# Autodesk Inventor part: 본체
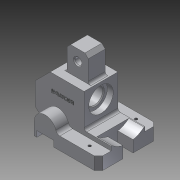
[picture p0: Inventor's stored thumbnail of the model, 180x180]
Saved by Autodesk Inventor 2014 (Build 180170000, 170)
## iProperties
Created: 2016-11
Part Number: 본체
Material: Aluminum 6061
Document SubType Name: Modeling
Designer: user
Density: 2.71 g/cm^3
Appearance: Aluminum - Flat
Mass: 462.896 g
Surface Area: 317.14 cm^2
Volume: 170.81 cm^3
Author: user
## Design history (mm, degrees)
sketch "Sketch2"
  geometry: L1 (0, 0)-(63, 0); L2 (-13, 15)-(13, 15); L3 (-13, 15)-(-13, 0); L4 (0, 0)-(-13, 0); L5 (-10, 0)-(-10, 7); L6 (-10, 7)-(10, 7); L7 (10, 7)-(10, 0); L8 (13, 15)-(38.139, 15); L9 (-13, 0)-(-10, 0); L10 (63, 0)-(63, 15); L11 (38.139, 15)-(63, 15); A1 r 13 centre (0, 15) between (13, 15) and (-13, 15); 2 further points
  constraints: 22 end point, 7 perpendicular, 2 midpoint, 2 point on circle, 2 point on line, 1 centre point, 1 coincident, 1 collinear, 1 horizontal, 1 parallel, 1 tangent, 1 vertical alignment
  dimensions: "d0" = 26 diameter of A1; "d1" = 15 distance of L1.start A1.centre; "d2" = 7 distance of L5.start L5.end; "d3" = 20 distance of L5.end L6.end; "d4" = 63 distance of L1.end L1.start; "d5" = 15 distance of L1.end L10.end; "d6" = 3 distance between parallel lines of L5 L3
extrude "Extrusion1" new body sketch "Sketch2" stored distance "d7" = 70; taper "d8" = 0 deg
fillet "Fillet1" dims "d9" = 5
sketch "Sketch3"
  geometry: L1 (17.292, 15)-(63, 15) reference; L2 (63, 15)-(63, 0) reference; L3 (-13, 0)-(-13, 15) reference; L4 (63, 15)-(63, 20); L5 (-27, 12)-(-27, 42); L6 (31, 20)-(31, 60); L7 (26, 42)-(26, 60); L8 (-9, 60)-(31, 60); L9 (63, 0)-(10, 0) reference; L10 (-27, 12)-(-13, 12); L11 (-27, 42)-(31, 42); L12 (-27, 42)-(-9, 60); L13 (63, 15)-(17.292, 15) reference; L14 (31, 20)-(63, 20); A1 r 13 centre (0, 15) between (12.488, 18.611) and (-13, 15) reference; A2 r 5 centre (17.292, 20) between (12.488, 18.611) and (17.292, 15) reference; 3 further points
  constraints: 18 end point, 7 parallel, 5 point on line, 1 horizontal alignment, 1 perpendicular
  dimensions: "d10" = 5 distance of L4.end L1.end; "d11" = 90 distance between parallel lines of L2 L5; "d12" = 58 distance between parallel lines of L6 L5; "d13" = 5 distance between parallel lines of L6 L7; "d14" = 60 distance between parallel lines of L9 L8; "d15" = 48 distance between parallel lines of L10 L8; "d16" = 30 distance between parallel lines of L11 L10; "d17" = 45 deg angle of L12 L8
extrude "Extrusion2" join sketch "Sketch3" stored distance "d18" = 40; taper "d19" = 0 deg
chamfer "Chamfer1" distance "d20" = 4; stored, may be unused: second distance "d21" = 2, angle "d22" = 45 deg
sketch "Sketch5"
  geometry: L1 (55, -15)-(-15, -15) reference; C1 r 14.5 at (20, 27); 3 further points
  constraints: 1 centre point, 1 coincident, 1 midpoint, 1 vertical alignment
  dimensions: "d24" = 42 distance from line of L1 point (20, 27); "d25" = 29 diameter of C1
extrude "Extrusion3" cut sketch "Sketch5" distance "d26" = 7; taper "d27" = 0 deg
sketch "Sketch6"
  geometry: C1 r 14.5 at (0, 0) reference; C2 r 10 at (0, 0); 1 further point
  constraints: 1 centre point, 1 coincident
  dimensions: "d28" = 20 diameter of C2
extrude "Extrusion4" cut sketch "Sketch6" distance "d29" = 64; taper "d30" = 0 deg
chamfer "Chamfer2" distance "d31" = 1; stored, may be unused: second distance "d32" = 2, angle "d33" = 45 deg
sketch "Sketch4"
  geometry: L1 (31, 60)-(31, 20) reference; L2 (26, 90)-(26, 60); L3 (1, 90)-(26, 90); L4 (-9, 60)-(31, 60) reference; L5 (1, 90)-(1, 60); 2 further points
  constraints: 6 end point, 2 perpendicular, 2 point on line, 1 parallel
  dimensions: "d23" = 5 distance between parallel lines of L1 L2; "d34" = 90 distance from line of point (0, 0) L3; "d35" = 25 distance between parallel lines of L2 L5
extrude "Extrusion5" join sketch "Sketch4" stored distance "d36" = 20; taper "d37" = 0 deg
sketch "Sketch7"
  geometry: L1 (1, 90)-(1, 60) reference; L2 (31, 20)-(31, 60) reference; L3 (26, 60)-(1, 60) reference; 4 further points
  constraints: 1 midpoint
  dimensions: "d38" = 12.5 distance from line of point (13.5, 77) L1; "d77" = 17 distance from line of L3 point (13.5, 77)
hole "Hole1" sketch "Sketch7" at (13.5, 77) diameter "d39" = 8; stored, may be unused: countersink angle "d43" = 90 deg, drill point angle "d45" = 0 deg; dims "d40" = 6, "d41" = 4, "d42" = 2, "d44" = 8
chamfer "Chamfer3" distance "d46" = 1; stored, may be unused: second distance "d47" = 2, angle "d48" = 45 deg
chamfer "Chamfer4" distance "d49" = 4; stored, may be unused: second distance "d50" = 2, angle "d51" = 45 deg
sketch "Sketch10"
  geometry: L1 (45.708, 0)-(45.708, 15) reference; L2 (45.708, 55)-(45.708, 70) reference; L3 (45.708, 55)-(45.708, 15) reference; 4 further points
  constraints: 1 horizontal alignment, 1 midpoint
  dimensions: "d53" = 18 distance from line of L1 point (27.708, 7.5); "d54" = 18 distance from line of L2 point (27.708, 62.5); "d55" = 55 distance of point (27.708, 7.5) point (27.708, 62.5)
hole "Hole2" sketch "Sketch10" at (27.708, 62.5), (27.708, 7.5) diameter "d56" = 3.242; stored, may be unused: countersink angle "d60" = 90 deg, drill point angle "d62" = 0 deg; dims "d57" = 6, "d58" = 4, "d59" = 2, "d61" = 8
sketch "Sketch11"
  geometry: L1 (55, 20)-(15, 20) reference; L2 (29, -16.373)-(41, -16.373); L3 (41, -16.373)-(41, 13.627); L4 (29, 13.627)-(29, -16.373); L5 (29, -16.373)-(39.918, 13.42); L6 (41, -16.373)-(29.598, 14.741); C1 r 10 at (35, 42) reference; A1 r 29 centre (35, 42) between (16.106, 20) and (53.894, 20); 2 further points
  constraints: 10 end point, 5 point on circle, 4 point on line, 1 centre point, 1 coincident, 1 horizontal, 1 midpoint, 1 parallel, 1 perpendicular, 1 vertical alignment
  dimensions: "d63" = 12 distance of L2.start L2.end; "d64" = 58 diameter of A1; "d65" = 30 distance of L2.end L3.end
extrude "Extrusion6" cut sketch "Sketch11" distance "d66" = 18; taper "d67" = 0 deg
fillet "Fillet2" dims "d68" = 3
workplane "Work Plane1"
sketch "Sketch12"
  geometry: L1 (31, 23)-(31, 60) reference; L2 (31, 60)-(-9, 60) reference; 2 further points
  constraints: 1 other
  dimensions: "d70" = 25 distance from line of L1 point (6, 42); "d71" = 18 distance from line of point (6, 42) L2
emboss "Emboss1" sketch "Sketch12" dims "d0" = 26, "d1" = 15, "d2" = 7, "d3" = 20, "d4" = 63, "d5" = 15, "d6" = 3, "d72" = 0.5, "d73" = 0
chamfer "Chamfer5" distance "d74" = 5; stored, may be unused: second distance "d75" = 2, angle "d76" = 45 deg
body "Solid1"
other parameters: "d69" = 64.25
